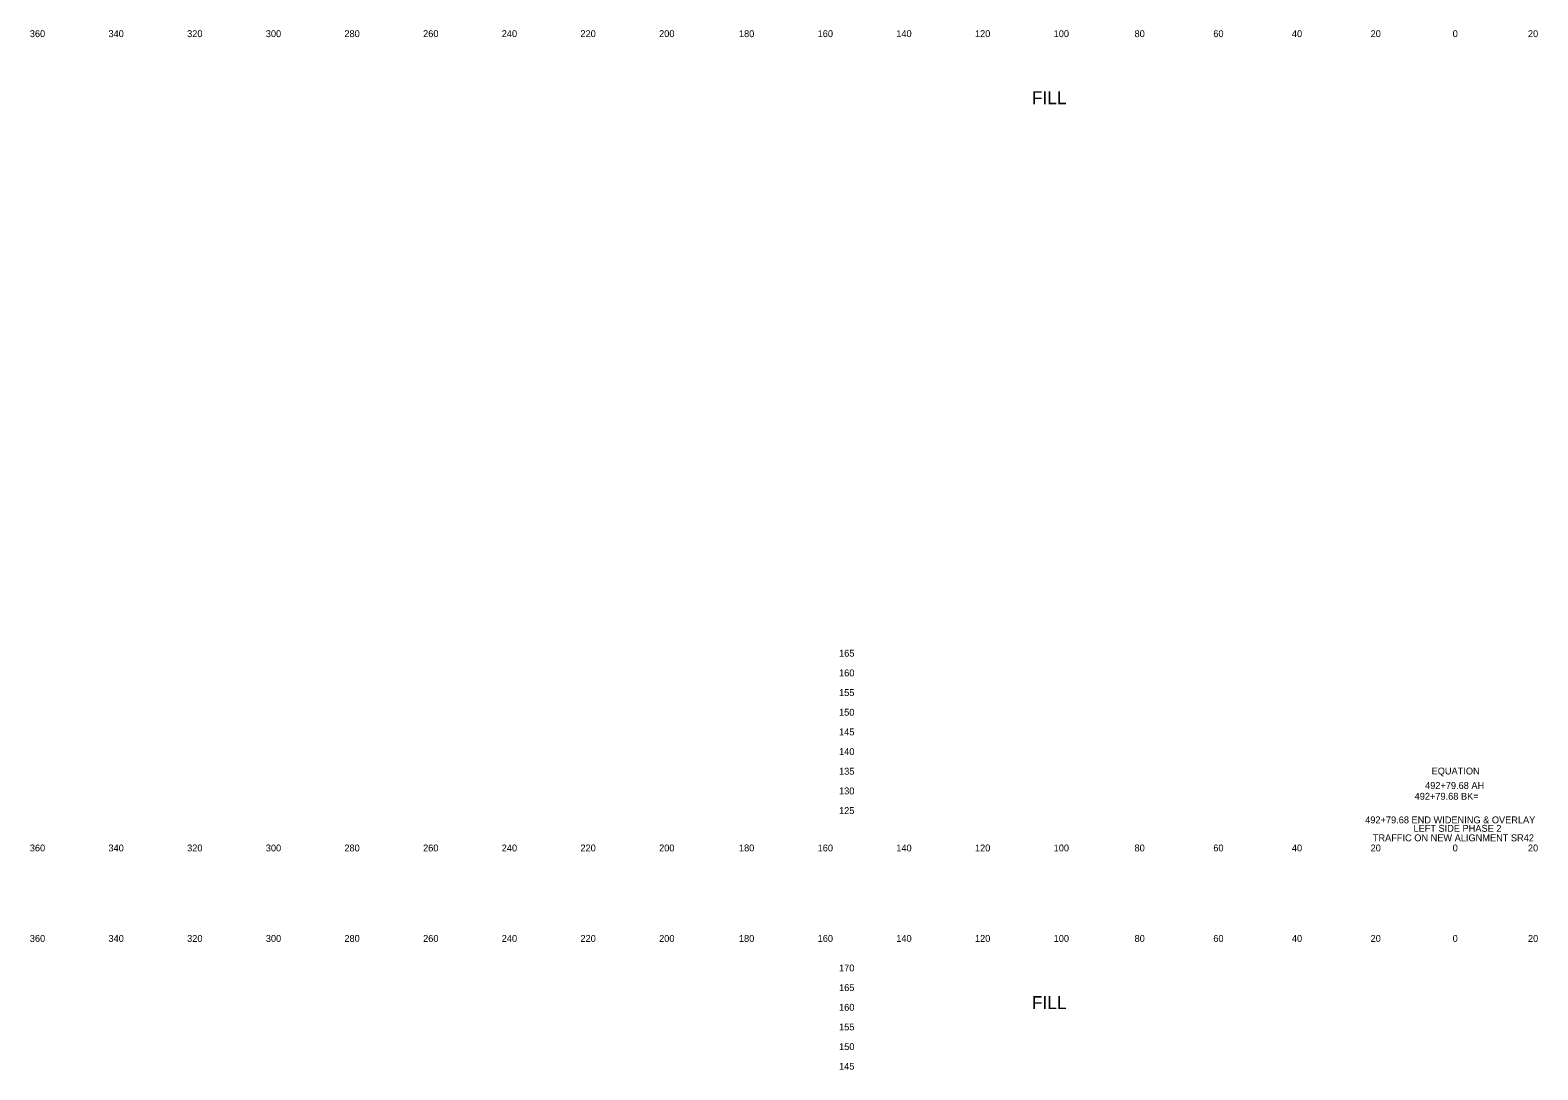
# Model space of a CAD drawing. Extents: x 21281 to 22024, y 6472 to 15208.
# Drawn here: x 21280.5 to 21663.8, y 14929.8 to 15194.1 of the extents above; entities that cross this region are included whole.
import ezdxf

# ---------------------------------------------------------------- set-up
doc = ezdxf.new("R2010")
doc.units = 0
for name, color, linetype in [('XS_SHEET_LABELS_ELEVATION', 7, 'Continuous'), ('XS_SHEET_LABELS_OFFSET', 7, 'Continuous'), ('XS_SHEET_LABELS_STATION', 7, 'Continuous')]:
    doc.layers.add(name, color=color, linetype=linetype)

msp = doc.modelspace()

# ---------------------------------------------------------------- texts
at = {"layer": 'XS_SHEET_LABELS_ELEVATION'}
for s, p in [('  165  ', (21484.84, 15034.84)), ('  160  ', (21484.84, 15029.84)), ('  155  ', (21484.84, 15024.84)), ('  150  ', (21484.84, 15019.84)), ('  145  ', (21484.84, 15014.84)), ('  140  ', (21484.84, 15009.84)), ('  135  ', (21484.84, 15004.84)), ('  130  ', (21484.84, 14999.84)), ('  125  ', (21484.84, 14994.84)), ('  170  ', (21484.84, 14954.84)), ('  165  ', (21484.84, 14949.84)), ('  160  ', (21484.84, 14944.84)), ('  155  ', (21484.84, 14939.84)), ('  150  ', (21484.84, 14934.84)), ('  145  ', (21484.84, 14929.84))]:
    msp.add_text(s, height=1.75, dxfattribs=at).set_placement(p)
at = {"layer": 'XS_SHEET_LABELS_OFFSET'}
for s, height, p in [('  360  ', 1.75, (21279.14, 15192.34)), ('  340  ', 1.75, (21299.13, 15192.34)), ('  320  ', 1.75, (21319.13, 15192.34)), ('  300  ', 1.75, (21339.13, 15192.34)), ('  280  ', 1.75, (21359.1, 15192.34)), ('  260  ', 1.75, (21379.11, 15192.34)), ('  240  ', 1.75, (21399.1, 15192.34)), ('  220  ', 1.75, (21419.1, 15192.34)), ('  200  ', 1.75, (21439.1, 15192.34)), ('  180  ', 1.75, (21459.39, 15192.34)), ('  160  ', 1.75, (21479.4, 15192.34)), ('  140  ', 1.75, (21499.39, 15192.34)), ('  120  ', 1.75, (21519.39, 15192.34)), ('  100  ', 1.75, (21539.39, 15192.34)), ('  80  ', 1.75, (21559.95, 15192.34)), ('  60  ', 1.75, (21579.97, 15192.34)), ('  40  ', 1.75, (21599.95, 15192.34)), ('  20  ', 1.75, (21619.95, 15192.34)), ('  0  ', 1.75, (21640.81, 15192.34)), ('  0  ', 1.75, (21640.81, 15192.34)), ('  20  ', 1.75, (21659.95, 15192.34)), ('FILL', 3.273, (21535.18, 15175.29)), ('  360  ', 1.75, (21279.14, 14985.34)), ('  340  ', 1.75, (21299.13, 14985.34)), ('  320  ', 1.75, (21319.13, 14985.34)), ('  300  ', 1.75, (21339.13, 14985.34)), ('  280  ', 1.75, (21359.1, 14985.34)), ('  260  ', 1.75, (21379.11, 14985.34)), ('  240  ', 1.75, (21399.1, 14985.34)), ('  220  ', 1.75, (21419.1, 14985.34)), ('  200  ', 1.75, (21439.1, 14985.34)), ('  180  ', 1.75, (21459.39, 14985.34)), ('  160  ', 1.75, (21479.4, 14985.34)), ('  140  ', 1.75, (21499.39, 14985.34)), ('  120  ', 1.75, (21519.39, 14985.34)), ('  100  ', 1.75, (21539.39, 14985.34)), ('  80  ', 1.75, (21559.95, 14985.34)), ('  60  ', 1.75, (21579.97, 14985.34)), ('  40  ', 1.75, (21599.95, 14985.34)), ('  20  ', 1.75, (21619.95, 14985.34)), ('  0  ', 1.75, (21640.81, 14985.34)), ('  0  ', 1.75, (21640.81, 14985.34)), ('  20  ', 1.75, (21659.95, 14985.34)), ('  360  ', 1.75, (21279.14, 14962.34)), ('  340  ', 1.75, (21299.13, 14962.34)), ('  320  ', 1.75, (21319.13, 14962.34)), ('  300  ', 1.75, (21339.13, 14962.34)), ('  280  ', 1.75, (21359.1, 14962.34)), ('  260  ', 1.75, (21379.11, 14962.34)), ('  240  ', 1.75, (21399.1, 14962.34)), ('  220  ', 1.75, (21419.1, 14962.34)), ('  200  ', 1.75, (21439.1, 14962.34)), ('  180  ', 1.75, (21459.39, 14962.34)), ('  160  ', 1.75, (21479.4, 14962.34)), ('  140  ', 1.75, (21499.39, 14962.34)), ('  120  ', 1.75, (21519.39, 14962.34)), ('  100  ', 1.75, (21539.39, 14962.34)), ('  80  ', 1.75, (21559.95, 14962.34)), ('  60  ', 1.75, (21579.97, 14962.34)), ('  40  ', 1.75, (21599.95, 14962.34)), ('  20  ', 1.75, (21619.95, 14962.34)), ('  0  ', 1.75, (21640.81, 14962.34)), ('  0  ', 1.75, (21640.81, 14962.34)), ('  20  ', 1.75, (21659.95, 14962.34)), ('FILL', 3.273, (21535.18, 14945.29))]:
    msp.add_text(s, height=height, dxfattribs=at).set_placement(p)
at = {"layer": 'XS_SHEET_LABELS_STATION'}
for s, p in [('EQUATION', (21636.76, 15004.9)), ('  492+79.68 BK= ', (21631.14, 14998.48)), ('492+79.68 AH', (21635.1, 15001.22)), (' 492+79.68 END WIDENING & OVERLAY', (21619.23, 14992.48)), ('TRAFFIC ON NEW ALIGNMENT SR42', (21621.82, 14987.92)), ('LEFT SIDE PHASE 2', (21632.14, 14990.33))]:
    msp.add_text(s, height=1.75, dxfattribs=at).set_placement(p)

doc.saveas('drawing.dxf')
